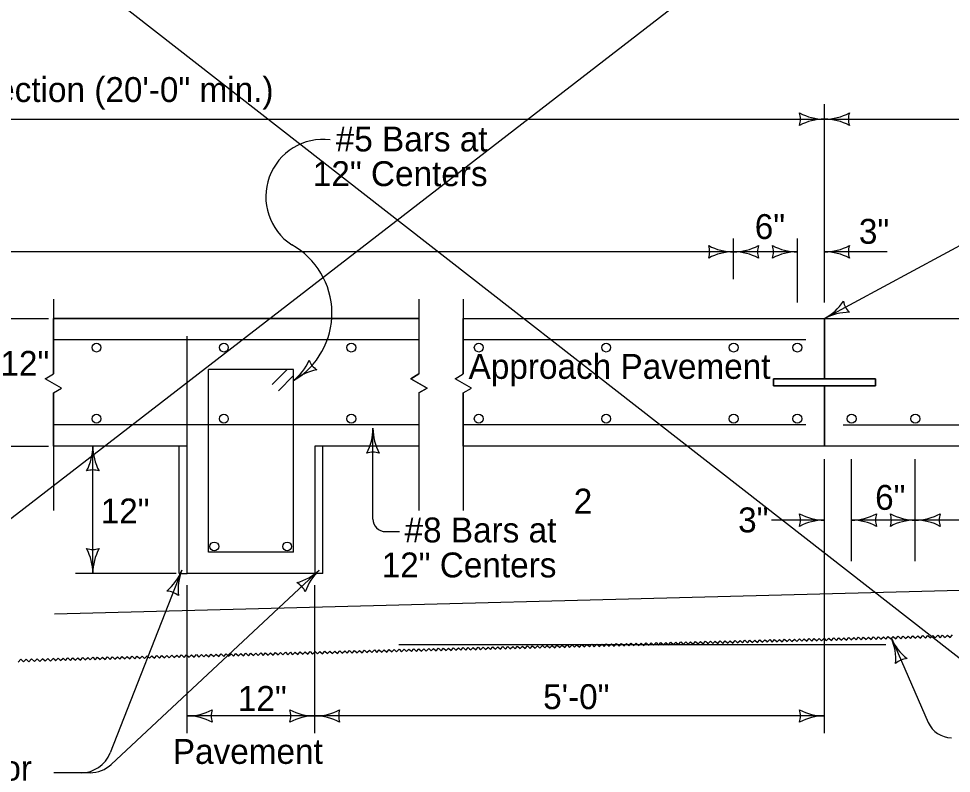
# Model space of a CAD drawing. Extents: x 8925 to 81668, y 4369 to 11918.
# Drawn here: x 11275 to 12023, y 5481 to 6087 of the extents above; entities that cross this region are included whole.
import ezdxf

# ---------------------------------------------------------------- set-up
doc = ezdxf.new("R2010")
doc.units = 0
for name, color, linetype in [('dsnShtPlotShapeBatchPrint', 7, 'Continuous'), ('dsnStdBorder', 7, 'Continuous'), ('Level 2', 7, 'Continuous'), ('Level 3', 7, 'Continuous'), ('SheetBorder', 7, 'Continuous')]:
    doc.layers.add(name, color=color, linetype=linetype)

msp = doc.modelspace()

# ---------------------------------------------------------------- linework, layer by layer
at = {"layer": 'dsnShtPlotShapeBatchPrint'}
for p, q in [((11921.46, 5859.08), (11921.46, 6018.29)), ((10549.21, 6006.24), (11921.46, 6006.24)), ((11921.46, 6006.24), (12890.09, 6006.24)), ((11921.46, 5846.04), (12084.65, 5934.37)), ((11848.52, 5877.7), (11848.52, 5910.27)), ((11899.68, 5859.08), (11899.68, 5910.27)), ((11848.52, 5899.68), (11222.55, 5899.68)), ((11899.68, 5899.68), (11848.52, 5899.68)), ((11971.86, 5899.68), (11921.46, 5899.68)), ((11198.03, 5846.04), (11298.42, 5846.04)), ((11302.49, 5801.59), (11302.49, 5846.04)), ((11302.49, 5846.04), (11595.92, 5846.04)), ((11595.92, 5846.04), (11595.92, 5801.59)), ((11631.44, 5801.59), (11631.44, 5846.04)), ((11631.44, 5846.04), (11921.46, 5846.04)), ((11631.44, 5846.04), (11921.46, 5846.04)), ((11921.46, 5846.04), (11921.46, 5797.72)), ((11921.46, 5797.72), (11921.46, 5846.04)), ((11921.46, 5846.04), (12397.85, 5846.04)), ((11921.46, 5846.04), (12397.85, 5846.04)), ((11921.46, 5797.72), (11921.46, 5846.04)), ((11409.93, 5669.07), (11409.93, 5832.01)), ((11631.44, 5801.6), (11631.44, 5801.59)), ((11921.46, 5797.72), (11880.54, 5797.73)), ((11880.54, 5797.73), (11880.54, 5792.04)), ((11880.54, 5797.73), (11880.54, 5792.04)), ((11962.38, 5797.73), (11921.46, 5797.72)), ((11962.38, 5792.04), (11962.38, 5797.73)), ((11962.38, 5792.04), (11962.38, 5797.73)), ((11880.54, 5792.04), (11921.46, 5792.04)), ((11962.38, 5792.04), (11880.54, 5792.04)), ((11921.46, 5792.04), (11921.46, 5743.73)), ((11921.46, 5743.73), (11921.46, 5792.04)), ((11921.46, 5792.04), (11962.38, 5792.04)), ((11921.46, 5743.73), (11921.46, 5792.04)), ((11302.49, 5743.73), (11302.49, 5786.44)), ((11595.92, 5786.43), (11595.92, 5743.73)), ((11631.44, 5743.73), (11631.44, 5786.43)), ((11558.98, 5685.11), (11558.98, 5758)), ((11197.33, 5743.73), (11298.42, 5743.73)), ((11409.93, 5743.73), (11302.49, 5743.73)), ((11334.08, 5641.43), (11334.08, 5743.73)), ((11409.93, 5641.43), (11409.93, 5743.73)), ((11512.24, 5743.74), (11512.24, 5641.43)), ((11595.92, 5743.73), (11512.24, 5743.73)), ((11512.24, 5743.73), (11512.24, 5641.43)), ((11921.46, 5743.73), (11631.44, 5743.73)), ((11921.46, 5743.73), (11631.44, 5743.73)), ((12397.85, 5743.73), (11921.46, 5743.73)), ((12397.85, 5743.73), (11921.46, 5743.73)), ((11921.46, 5513.21), (11921.46, 5733.24)), ((11943.24, 5651.23), (11943.24, 5733.24)), ((11994.4, 5651.23), (11994.4, 5733.24)), ((11921.46, 5684.23), (11878.83, 5684.23)), ((11994.4, 5684.23), (11943.24, 5684.23)), ((12817.15, 5684.23), (11994.4, 5684.23)), ((11569.09, 5675), (11580.34, 5675)), ((11400.96, 5641.43), (11320.16, 5641.43)), ((11405.47, 5644.02), (11347.93, 5497.22)), ((11515.84, 5644.02), (11348.92, 5488.07)), ((11512.24, 5641.43), (11409.93, 5641.43)), ((11303.23, 5608.93), (12398.22, 5637.52)), ((11409.94, 5513.21), (11409.94, 5632.01)), ((11512.24, 5513.21), (11512.24, 5632.01)), ((11975.15, 5589.36), (12004.8, 5521.61)), ((11512.24, 5526.98), (11409.93, 5526.98)), ((11921.46, 5526.98), (11512.24, 5526.98)), ((11331.85, 5481.34), (11302.89, 5481.34))]:
    msp.add_line(p, q, dxfattribs=at)
for points in [[(11302.49, 5786.44), (11309.05, 5790.22), (11295.92, 5797.81), (11302.49, 5801.6)], [(11595.92, 5801.6), (11589.35, 5797.81), (11602.48, 5790.22), (11595.92, 5786.44)], [(11631.44, 5786.44), (11638.01, 5790.22), (11624.87, 5797.81), (11631.44, 5801.6)], [(11779.32, 5584.68), (11780.33, 5583.71), (11782.26, 5585.75), (11784.3, 5583.82), (11786.24, 5585.85), (11788.27, 5583.92), (11790.2, 5585.96), (11792.24, 5584.03), (11794.17, 5586.06), (11796.21, 5584.13), (11798.14, 5586.16), (11800.17, 5584.23), (11802.1, 5586.27), (11804.14, 5584.34), (11806.07, 5586.37), (11808.1, 5584.44), (11810.04, 5586.47), (11812.07, 5584.55), (11814, 5586.58), (11816.04, 5584.65), (11817.97, 5586.68), (11820, 5584.75), (11821.94, 5586.79), (11823.97, 5584.85), (11825.91, 5586.89), (11826.92, 5585.92)], [(11826.92, 5585.92), (11827.94, 5584.96), (11829.87, 5586.99), (11831.91, 5585.06), (11833.84, 5587.1), (11835.88, 5585.16), (11837.81, 5587.2), (11839.84, 5585.27), (11841.78, 5587.3), (11843.81, 5585.37), (11845.74, 5587.41), (11847.78, 5585.48), (11849.71, 5587.51), (11851.75, 5585.58), (11853.68, 5587.61), (11855.72, 5585.69), (11857.65, 5587.72), (11859.68, 5585.79), (11861.61, 5587.82), (11863.65, 5585.89), (11865.58, 5587.92), (11867.61, 5585.99), (11869.55, 5588.03), (11871.58, 5586.1), (11873.51, 5588.13), (11874.53, 5587.17)], [(11874.53, 5587.17), (11875.55, 5586.2), (11877.48, 5588.24), (11879.52, 5586.3), (11881.45, 5588.34), (11883.48, 5586.41), (11885.41, 5588.44), (11887.45, 5586.51), (11889.38, 5588.55), (11891.42, 5586.62), (11893.35, 5588.65), (11895.38, 5586.72), (11897.32, 5588.75), (11899.36, 5586.83), (11901.29, 5588.86), (11903.32, 5586.93), (11905.25, 5588.96), (11907.29, 5587.03), (11909.22, 5589.06), (11911.26, 5587.13), (11913.19, 5589.17), (11915.22, 5587.24), (11917.16, 5589.27), (11919.19, 5587.34), (11921.12, 5589.37), (11922.14, 5588.41)], [(11922.14, 5588.41), (11923.15, 5587.44), (11925.09, 5589.48), (11927.12, 5587.55), (11929.05, 5589.58), (11931.09, 5587.65), (11933.02, 5589.69), (11935.06, 5587.76), (11936.99, 5589.79), (11939.03, 5587.86), (11940.96, 5589.89), (11943, 5587.96), (11944.93, 5590), (11946.96, 5588.07), (11948.89, 5590.1), (11950.93, 5588.17), (11952.86, 5590.2), (11954.9, 5588.27), (11956.83, 5590.31), (11958.87, 5588.38), (11960.8, 5590.41), (11962.83, 5588.48), (11964.76, 5590.51), (11966.8, 5588.58), (11968.73, 5590.62), (11969.75, 5589.66)], [(11969.75, 5589.66), (11970.76, 5588.69), (11972.7, 5590.72), (11974.73, 5588.79), (11976.67, 5590.83), (11978.7, 5588.9), (11980.63, 5590.93), (11982.66, 5589), (11984.6, 5591.03), (11986.63, 5589.1), (11988.57, 5591.13), (11990.6, 5589.21), (11992.53, 5591.24), (11994.57, 5589.31), (11996.5, 5591.34), (11998.54, 5589.41), (12000.47, 5591.44), (12002.5, 5589.52), (12004.44, 5591.55), (12006.47, 5589.62), (12008.41, 5591.65), (12010.44, 5589.72), (12012.37, 5591.76), (12014.41, 5589.82), (12016.34, 5591.86), (12017.36, 5590.89)], [(12017.36, 5590.89), (12018.38, 5589.93), (12020.3, 5591.97), (12022.34, 5590.03), (12024.27, 5592.07)], [(11493.66, 5577.22), (11494.68, 5576.25), (11496.61, 5578.29), (11498.65, 5576.36), (11500.59, 5578.39), (11502.62, 5576.46), (11504.55, 5578.5), (11506.59, 5576.57), (11508.52, 5578.6), (11510.55, 5576.67), (11512.49, 5578.7), (11514.52, 5576.77), (11516.45, 5578.81), (11518.49, 5576.88), (11520.42, 5578.91), (11522.45, 5576.98), (11524.39, 5579.01), (11526.42, 5577.09), (11528.36, 5579.11), (11530.39, 5577.19), (11532.32, 5579.22), (11534.35, 5577.29), (11536.29, 5579.33), (11538.33, 5577.39), (11540.25, 5579.43), (11541.27, 5578.46)], [(11541.27, 5578.46), (11542.29, 5577.5), (11544.22, 5579.53), (11546.26, 5577.6), (11548.19, 5579.64), (11550.23, 5577.7), (11552.16, 5579.74), (11554.19, 5577.81), (11556.13, 5579.84), (11558.16, 5577.91), (11560.1, 5579.95), (11562.13, 5578.01), (11564.06, 5580.05), (11566.1, 5578.12), (11568.03, 5580.15), (11570.07, 5578.23), (11572, 5580.25), (11574.03, 5578.33), (11575.96, 5580.36), (11578, 5578.43), (11579.93, 5580.46), (11581.96, 5578.53), (11583.9, 5580.57), (11585.93, 5578.64), (11587.86, 5580.67), (11588.88, 5579.7)], [(11588.88, 5579.7), (11589.9, 5578.74), (11591.83, 5580.77), (11593.87, 5578.84), (11595.8, 5580.88), (11597.83, 5578.95), (11599.76, 5580.98), (11601.8, 5579.05), (11603.74, 5581.09), (11605.77, 5579.15), (11607.7, 5581.19), (11609.74, 5579.26), (11611.67, 5581.29), (11613.7, 5579.36), (11615.64, 5581.39), (11617.68, 5579.47), (11619.6, 5581.5), (11621.64, 5579.57), (11623.57, 5581.6), (11625.61, 5579.67), (11627.54, 5581.71), (11629.58, 5579.78), (11631.51, 5581.81), (11633.54, 5579.88), (11635.48, 5581.91), (11636.49, 5580.95)], [(11636.49, 5580.95), (11637.5, 5579.99), (11639.44, 5582.02), (11641.47, 5580.09), (11643.41, 5582.12), (11645.44, 5580.19), (11647.37, 5582.23), (11649.41, 5580.29), (11651.34, 5582.33), (11653.38, 5580.4), (11655.31, 5582.44), (11657.34, 5580.5), (11659.28, 5582.53), (11661.31, 5580.61), (11663.24, 5582.64), (11665.28, 5580.71), (11667.21, 5582.74), (11669.25, 5580.81), (11671.18, 5582.85), (11673.22, 5580.92), (11675.15, 5582.95), (11677.18, 5581.02), (11679.11, 5583.05), (11681.15, 5581.13), (11683.08, 5583.16), (11684.1, 5582.19)], [(11684.1, 5582.19), (11685.12, 5581.23), (11687.05, 5583.26), (11689.08, 5581.33), (11691.02, 5583.37), (11693.05, 5581.43), (11694.98, 5583.47), (11697.02, 5581.54), (11698.95, 5583.58), (11700.98, 5581.64), (11702.92, 5583.67), (11704.95, 5581.75), (11706.88, 5583.78), (11708.92, 5581.85), (11710.85, 5583.88), (11712.89, 5581.95), (11714.82, 5583.99), (11716.85, 5582.06), (11718.79, 5584.09), (11720.82, 5582.16), (11722.76, 5584.19), (11724.79, 5582.27), (11726.72, 5584.29), (11728.76, 5582.37), (11730.69, 5584.4), (11731.71, 5583.43)], [(11731.71, 5583.43), (11732.72, 5582.47), (11734.66, 5584.51), (11736.69, 5582.57), (11738.62, 5584.61), (11740.66, 5582.68), (11742.59, 5584.71), (11744.63, 5582.78), (11746.56, 5584.81), (11748.59, 5582.89), (11750.53, 5584.92), (11752.56, 5582.99), (11754.5, 5585.02), (11756.53, 5583.09), (11758.46, 5585.13), (11760.5, 5583.2), (11762.43, 5585.23), (11764.46, 5583.3), (11766.39, 5585.33), (11768.43, 5583.41), (11770.36, 5585.44), (11772.4, 5583.51), (11774.33, 5585.54), (11776.37, 5583.61), (11778.3, 5585.65), (11779.32, 5584.68)], [(11303.46, 5572.12), (11302.35, 5573.18), (11300.22, 5570.95), (11297.98, 5573.07), (11295.86, 5570.84), (11293.62, 5572.95), (11291.51, 5570.72), (11289.27, 5572.84), (11287.14, 5570.61), (11284.91, 5572.73), (11282.78, 5570.5), (11280.55, 5572.61), (11278.43, 5570.38), (11276.19, 5572.5), (11274.07, 5570.27)], [(11303.23, 5572.24), (11304.25, 5571.28), (11306.18, 5573.32), (11308.22, 5571.39), (11310.15, 5573.42), (11312.19, 5571.49), (11314.12, 5573.52), (11316.15, 5571.59), (11318.08, 5573.62), (11320.12, 5571.7), (11322.05, 5573.73), (11324.09, 5571.8), (11326.02, 5573.84), (11328.05, 5571.9), (11329.98, 5573.94), (11332.03, 5572.01), (11333.96, 5574.04), (11335.99, 5572.11), (11337.92, 5574.14), (11339.96, 5572.21), (11341.89, 5574.25), (11343.92, 5572.32), (11345.86, 5574.35), (11347.9, 5572.42), (11349.82, 5574.45), (11350.84, 5573.49)], [(11350.84, 5573.49), (11351.86, 5572.53), (11353.79, 5574.56), (11355.83, 5572.63), (11357.76, 5574.66), (11359.79, 5572.73), (11361.73, 5574.76), (11363.76, 5572.84), (11365.69, 5574.87), (11367.73, 5572.94), (11369.66, 5574.98), (11371.69, 5573.04), (11373.63, 5575.08), (11375.66, 5573.15), (11377.6, 5575.18), (11379.63, 5573.25), (11381.56, 5575.28), (11383.6, 5573.35), (11385.53, 5575.39), (11387.57, 5573.46), (11389.5, 5575.49), (11391.53, 5573.56), (11393.46, 5575.59), (11395.5, 5573.67), (11397.43, 5575.7), (11398.45, 5574.73)], [(11398.45, 5574.73), (11399.47, 5573.77), (11401.4, 5575.8), (11403.44, 5573.87), (11405.37, 5575.91), (11407.41, 5573.97), (11409.33, 5576.01), (11411.37, 5574.08), (11413.3, 5576.12), (11415.33, 5574.18), (11417.27, 5576.22), (11419.3, 5574.29), (11421.24, 5576.32), (11423.27, 5574.39), (11425.2, 5576.42), (11427.24, 5574.49), (11429.17, 5576.53), (11431.21, 5574.6), (11433.14, 5576.63), (11435.17, 5574.7), (11437.11, 5576.73), (11439.14, 5574.81), (11441.07, 5576.84), (11443.11, 5574.91), (11445.04, 5576.94), (11446.06, 5575.98)], [(11446.06, 5575.98), (11447.07, 5575.01), (11449.01, 5577.05), (11451.05, 5575.11), (11452.97, 5577.15), (11455.01, 5575.22), (11456.94, 5577.25), (11458.98, 5575.32), (11460.91, 5577.36), (11462.95, 5575.43), (11464.88, 5577.46), (11466.91, 5575.53), (11468.85, 5577.56), (11470.88, 5575.63), (11472.81, 5577.67), (11474.85, 5575.73), (11476.78, 5577.77), (11478.81, 5575.84), (11480.74, 5577.87), (11482.78, 5575.95), (11484.71, 5577.98), (11486.75, 5576.05), (11488.68, 5578.08), (11490.72, 5576.15), (11492.65, 5578.19), (11493.66, 5577.22)]]:
    msp.add_lwpolyline(points, dxfattribs=at)
for centre, radius, start, end in [((11518.99, 5943.88), 46.06, 82.93387, 236.76687), ((11463.07, 5850.38), 62.96, 300.6735, 60.83314), ((11569.09, 5685.11), 10.1, 180, 270), ((12023.32, 5529.72), 20.21, 203.64012, 270)]:
    msp.add_arc(centre, radius, start, end, dxfattribs=at)
at = {"layer": 'dsnStdBorder'}
for p, q in [((11302.49, 5861.68), (11302.49, 5801.59)), ((11595.92, 5861.68), (11595.92, 5801.59)), ((11631.44, 5861.68), (11631.44, 5801.59)), ((11595.92, 5846.04), (11302.49, 5846.04)), ((11921.46, 5797.72), (11921.46, 5846.04)), ((11595.92, 5828.99), (11302.49, 5828.99)), ((11906.39, 5828.99), (11631.44, 5828.99)), ((11426.99, 5658.48), (11426.99, 5805.23)), ((11495.19, 5805.23), (11426.99, 5805.23)), ((11490.2, 5805.23), (11478.15, 5793.17)), ((11495.19, 5658.48), (11495.19, 5805.23)), ((11495.19, 5800.24), (11483.13, 5788.18)), ((11880.54, 5792.04), (11880.54, 5797.73)), ((11880.54, 5797.73), (11962.38, 5797.73)), ((11962.38, 5797.73), (11962.38, 5792.04)), ((11962.38, 5792.04), (11880.54, 5792.04)), ((11921.46, 5743.73), (11921.46, 5792.04)), ((11302.49, 5786.43), (11302.49, 5691.82)), ((11595.92, 5786.43), (11595.92, 5691.82)), ((11631.44, 5786.43), (11631.44, 5691.82)), ((11595.92, 5760.78), (11302.49, 5760.78)), ((11906.39, 5760.78), (11631.44, 5760.78)), ((11936.53, 5760.78), (12397.85, 5760.78)), ((11409.93, 5743.73), (11302.49, 5743.73)), ((11403.47, 5641.43), (11403.47, 5743.74)), ((11409.93, 5641.43), (11409.93, 5743.74)), ((11595.92, 5743.73), (11512.24, 5743.73)), ((11518.7, 5641.43), (11518.7, 5743.74)), ((11495.19, 5658.48), (11426.99, 5658.48)), ((11403.47, 5641.43), (11409.94, 5641.43)), ((11512.24, 5641.43), (11409.93, 5641.43)), ((11518.71, 5641.43), (11512.24, 5641.43)), ((11579.7, 5584.27), (11970.6, 5584.27))]:
    msp.add_line(p, q, dxfattribs=at)
for points in [[(11302.49, 5786.44), (11309.05, 5790.22), (11295.92, 5797.81), (11302.49, 5801.6)], [(11595.92, 5786.44), (11602.48, 5790.22), (11589.35, 5797.81), (11595.92, 5801.6)], [(11631.44, 5786.44), (11638.01, 5790.22), (11624.87, 5797.81), (11631.44, 5801.6)]]:
    msp.add_lwpolyline(points, dxfattribs=at)
for centre, radius, start, end in [((11468.63, 5829.42), 42.5, 308.6676, 336.74009), ((11523.01, 5818.5), 16.42, 200.93424, 236.40095), ((11521.74, 5763.05), 42.5, 100.59511, 128.6676), ((11324.66, 5506.34), 25, 270, 338.59752), ((11331.85, 5506.34), 25, 270, 313.05415)]:
    msp.add_arc(centre, radius, start, end, dxfattribs=at)
at = {"layer": 'Level 2'}
for centre in [(11337, 5822.78), (11439.3, 5822.78), (11541.61, 5822.78), (11643.91, 5822.78), (11746.22, 5822.78), (11848.52, 5822.78), (11899.68, 5822.78), (11337, 5765.68), (11439.3, 5765.68), (11541.61, 5765.68), (11643.91, 5765.68), (11746.22, 5765.68), (11848.52, 5765.68), (11899.68, 5765.68), (11943.24, 5765.68), (11994.4, 5765.68), (11431.58, 5663.1), (11490.12, 5663.1)]:
    msp.add_circle(centre, 3.55, dxfattribs=at)
at = {"layer": 'Level 3'}
for centre, radius, start, end in [((11885.82, 6006.24), 16.42, 342.26665, 17.73335), ((11921.46, 6048.74), 42.5, 241.92751, 270), ((11921.46, 5963.74), 42.5, 90, 118.07249), ((11921.46, 6048.74), 42.5, 270, 298.07249), ((11921.46, 5963.74), 42.5, 61.92751, 90), ((11957.09, 6006.24), 16.42, 162.26665, 197.73335), ((11812.89, 5899.68), 16.42, 342.26665, 17.73335), ((11848.52, 5942.18), 42.5, 241.92751, 270), ((11848.52, 5942.18), 42.5, 270, 298.07249), ((11884.16, 5899.68), 16.42, 162.26665, 197.73335), ((11864.04, 5899.68), 16.42, 342.26665, 17.73335), ((11899.68, 5942.18), 42.5, 241.92751, 270), ((11921.46, 5942.18), 42.5, 270, 298.07249), ((11957.09, 5899.68), 16.42, 162.26665, 197.73335), ((11848.52, 5857.18), 42.5, 90, 118.07249), ((11848.52, 5857.18), 42.5, 61.92751, 90), ((11899.68, 5857.18), 42.5, 90, 118.07249), ((11921.46, 5857.18), 42.5, 61.92751, 90), ((11901.23, 5883.41), 42.5, 298.42581, 326.4983), ((11952.8, 5863), 16.42, 190.69246, 226.15916), ((11941.69, 5808.66), 42.5, 90.35332, 118.42581), ((11516.48, 5758), 42.5, 331.92751, 360), ((11601.48, 5758), 42.5, 180, 208.07249), ((11291.58, 5743.73), 42.5, 331.92751, 360), ((11376.58, 5743.73), 42.5, 180, 208.07249), ((11558.98, 5722.36), 16.42, 72.26665, 107.73335), ((11334.08, 5708.1), 16.42, 72.26665, 107.73335), ((11885.82, 5684.23), 16.42, 342.26665, 17.73335), ((11921.46, 5726.73), 42.5, 241.92751, 270), ((11921.46, 5641.73), 42.5, 90, 118.07249), ((11943.24, 5726.73), 42.5, 270, 298.07249), ((11943.24, 5641.73), 42.5, 61.92751, 90), ((11978.88, 5684.23), 16.42, 162.26665, 197.73335), ((11958.76, 5684.23), 16.42, 342.26665, 17.73335), ((11994.4, 5726.73), 42.5, 241.92751, 270), ((11994.4, 5641.73), 42.5, 90, 118.07249), ((11994.4, 5726.73), 42.5, 270, 298.07249), ((11994.4, 5641.73), 42.5, 61.92751, 90), ((12030.03, 5684.23), 16.42, 162.26665, 197.73335), ((11334.08, 5677.06), 16.42, 252.26665, 287.73335), ((11291.58, 5641.43), 42.5, 360, 28.07249), ((11376.58, 5641.43), 42.5, 151.92751, 180), ((11365.9, 5659.53), 42.5, 310.52503, 338.59752), ((11445.04, 5628.51), 42.5, 158.59752, 186.67), ((11486.82, 5675.08), 42.5, 284.98166, 313.05415), ((11544.85, 5612.97), 42.5, 133.05415, 161.12664), ((11489.8, 5619.69), 16.42, 25.3208, 60.7875), ((11392.47, 5610.84), 16.42, 50.86416, 86.33087), ((12014.08, 5606.4), 42.5, 203.64012, 231.71261), ((11936.22, 5572.32), 42.5, 355.56763, 23.64012), ((11989.44, 5556.72), 16.42, 95.90677, 131.37347), ((11409.93, 5569.48), 42.5, 270, 298.07249), ((11409.93, 5484.48), 42.5, 61.92751, 90), ((11445.57, 5526.98), 16.42, 162.26665, 197.73335), ((11476.6, 5526.98), 16.42, 342.26665, 17.73335), ((11512.24, 5569.48), 42.5, 241.92751, 270), ((11512.24, 5484.48), 42.5, 90, 118.07249), ((11512.24, 5569.48), 42.5, 270, 298.07249), ((11512.24, 5484.48), 42.5, 61.92751, 90), ((11547.87, 5526.98), 16.42, 162.26665, 197.73335), ((11885.82, 5526.98), 16.42, 342.26665, 17.73335), ((11921.46, 5569.48), 42.5, 241.92751, 270), ((11921.46, 5484.48), 42.5, 90, 118.07249)]:
    msp.add_arc(centre, radius, start, end, dxfattribs=at)
at = {"layer": 'SheetBorder'}
for p, q in [((13555.2, 7452.02), (9727.11, 4495)), ((9794.95, 7316.28), (13574.58, 4368.96))]:
    msp.add_line(p, q, dxfattribs=at)

# ---------------------------------------------------------------- texts
at = {"layer": 'dsnShtPlotShapeBatchPrint'}
for s, p in [('Double Reinforced Section (20\'-0" min.)', (11009.68, 6019.98)), ('#5 Bars at', (11529.08, 5980.28)), ('12" Centers', (11510.7, 5952.45)), ('6"', (11865.49, 5909.95)), ('3"', (11949.08, 5906.14)), ('12"', (11259.88, 5800.1)), ('Approach Pavement', (11635.77, 5797.67)), ('2', (11720.17, 5689.44)), ('6"', (11962.12, 5692.48)), ('12"', (11340.36, 5681.54)), ('3"', (11852.15, 5674.38)), ('#8 Bars at', (11584.33, 5666.31)), ('12" Centers', (11565.94, 5638.22)), ('12"', (11450.51, 5531.02)), ('5\'-0"', (11695.6, 5532.43)), ('Pavement', (11398.3, 5488.47)), ('Form Board Required for', (10989.43, 5475.09))]:
    msp.add_text(s, height=20, dxfattribs=at).set_placement(p)

doc.saveas('drawing.dxf')
